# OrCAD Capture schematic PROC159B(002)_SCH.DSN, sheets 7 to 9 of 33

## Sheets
7 20. SOC-ICSS ETHERNET CONN: size C; title: SOC-ICSS ETHERNET CONN
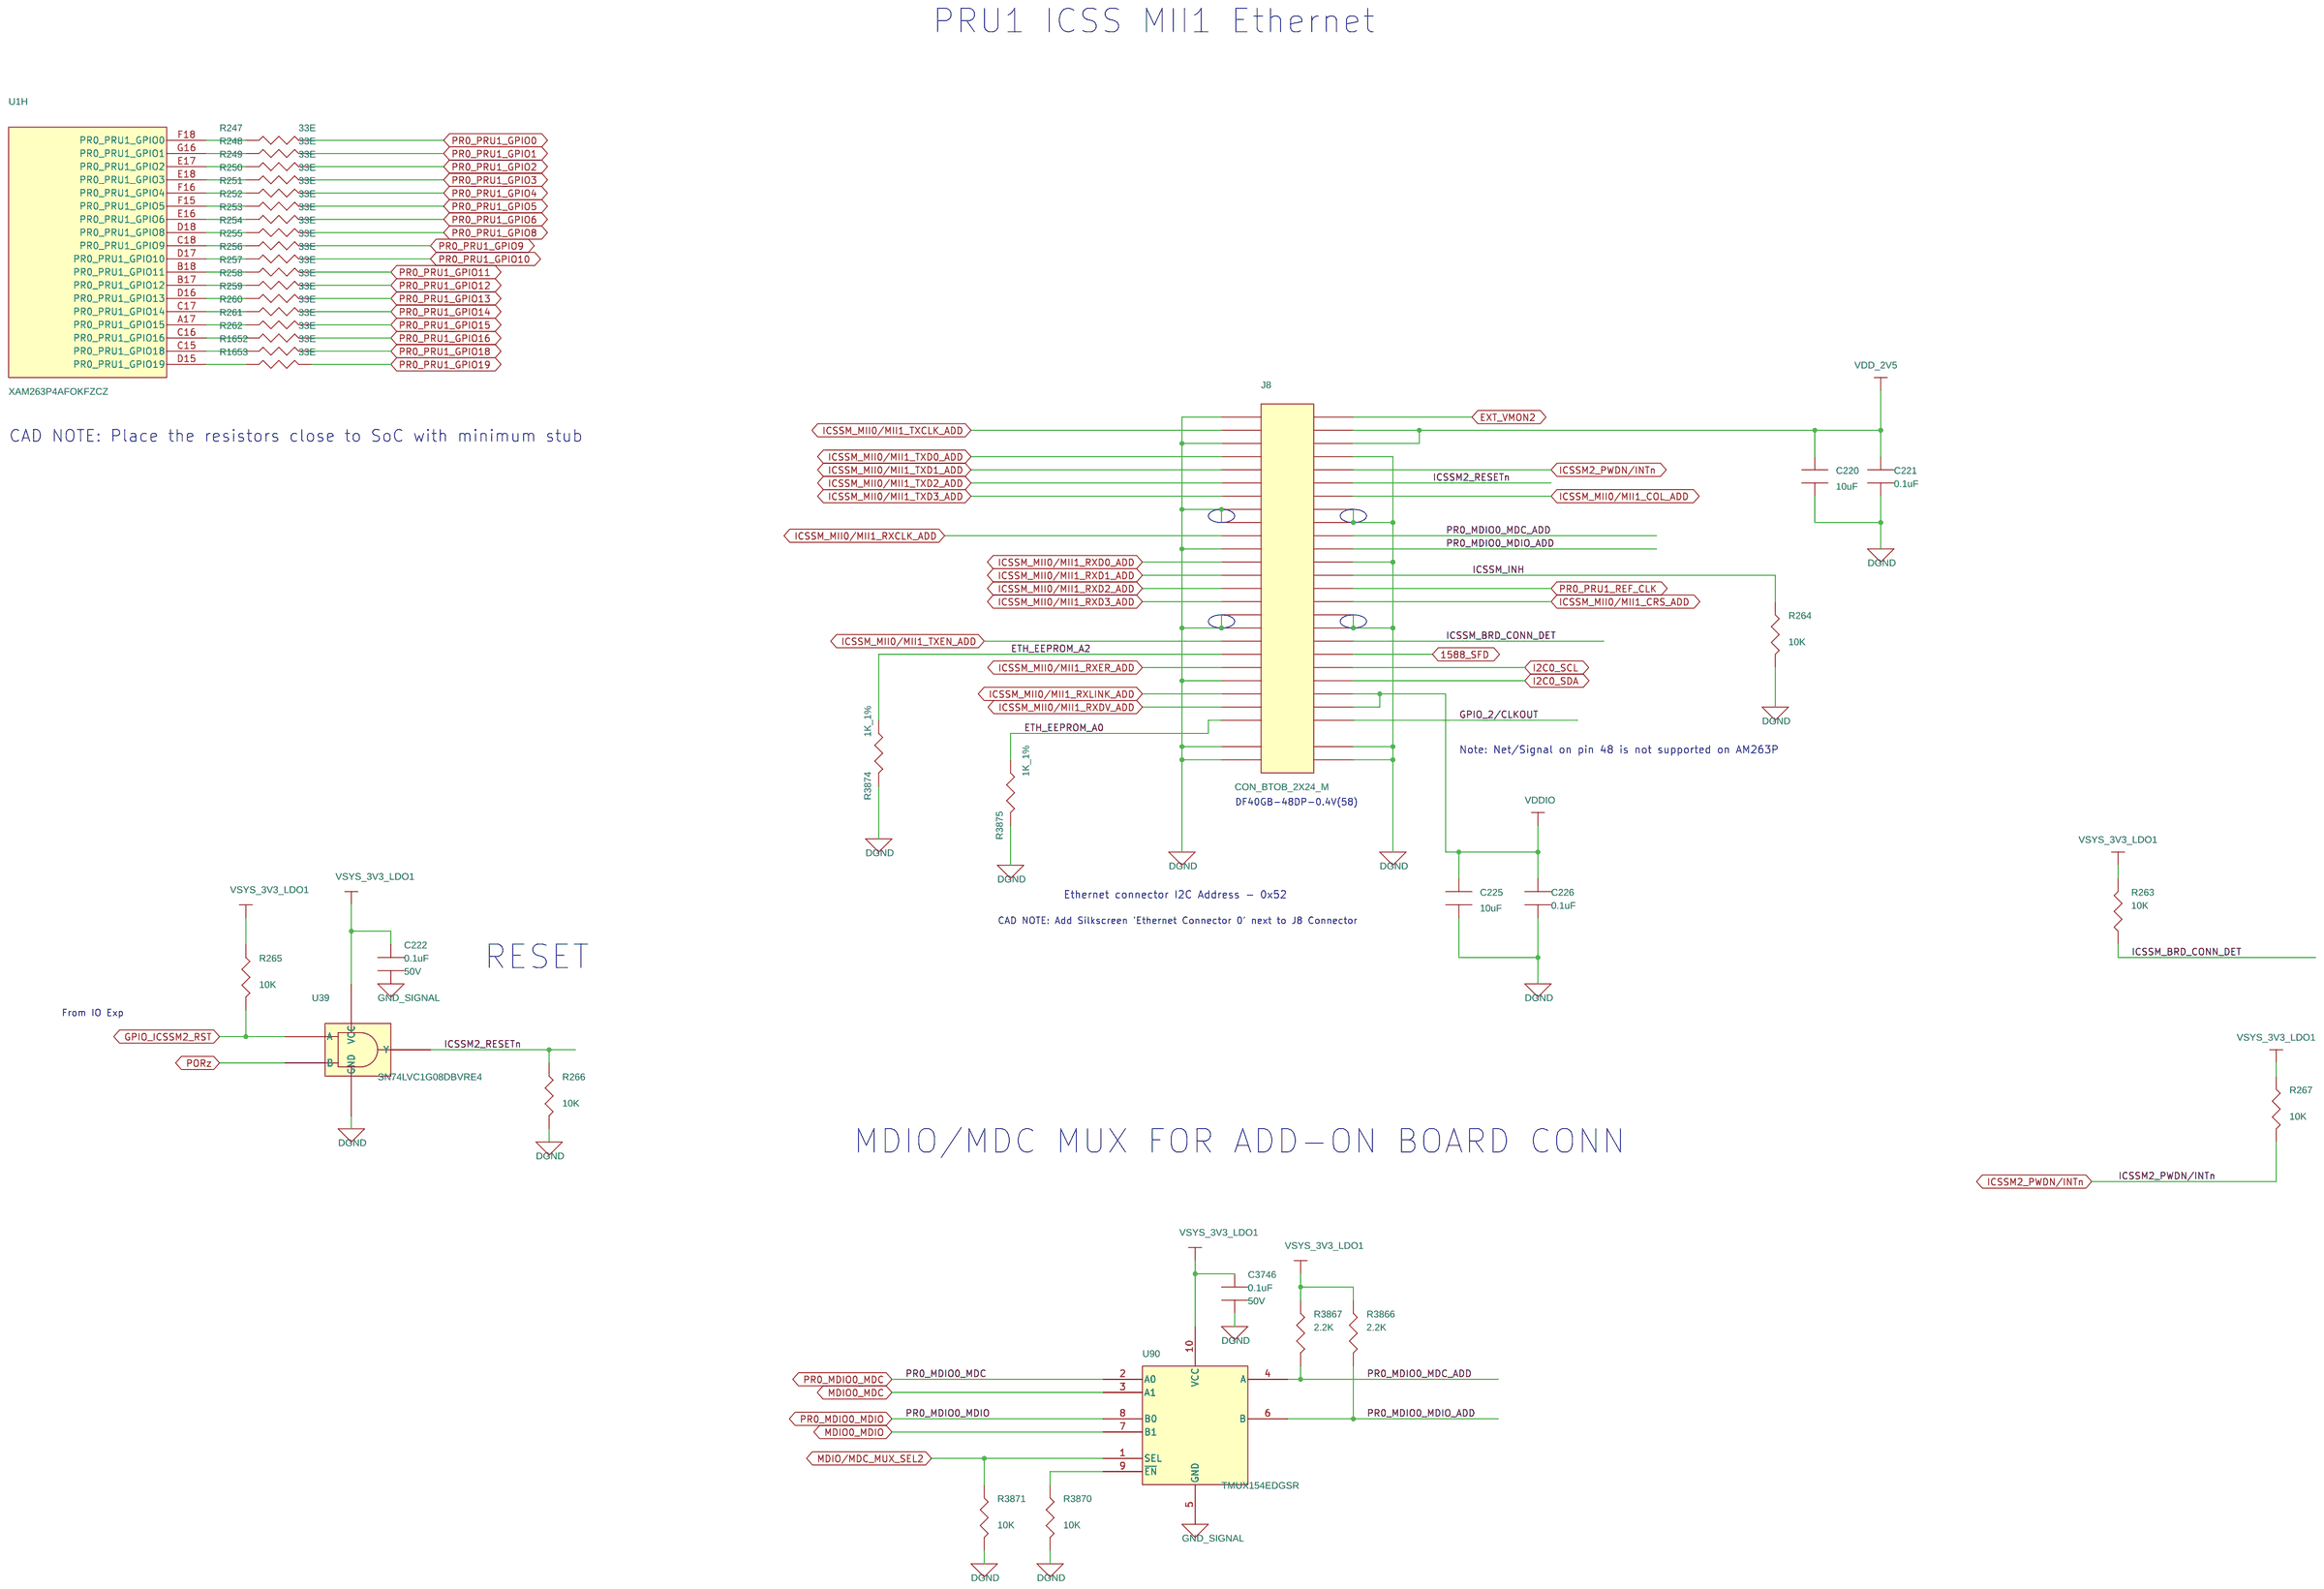
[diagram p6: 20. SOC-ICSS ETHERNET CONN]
8 13. SOC_POWER and GND: size C; title: SOC POWER AND GND
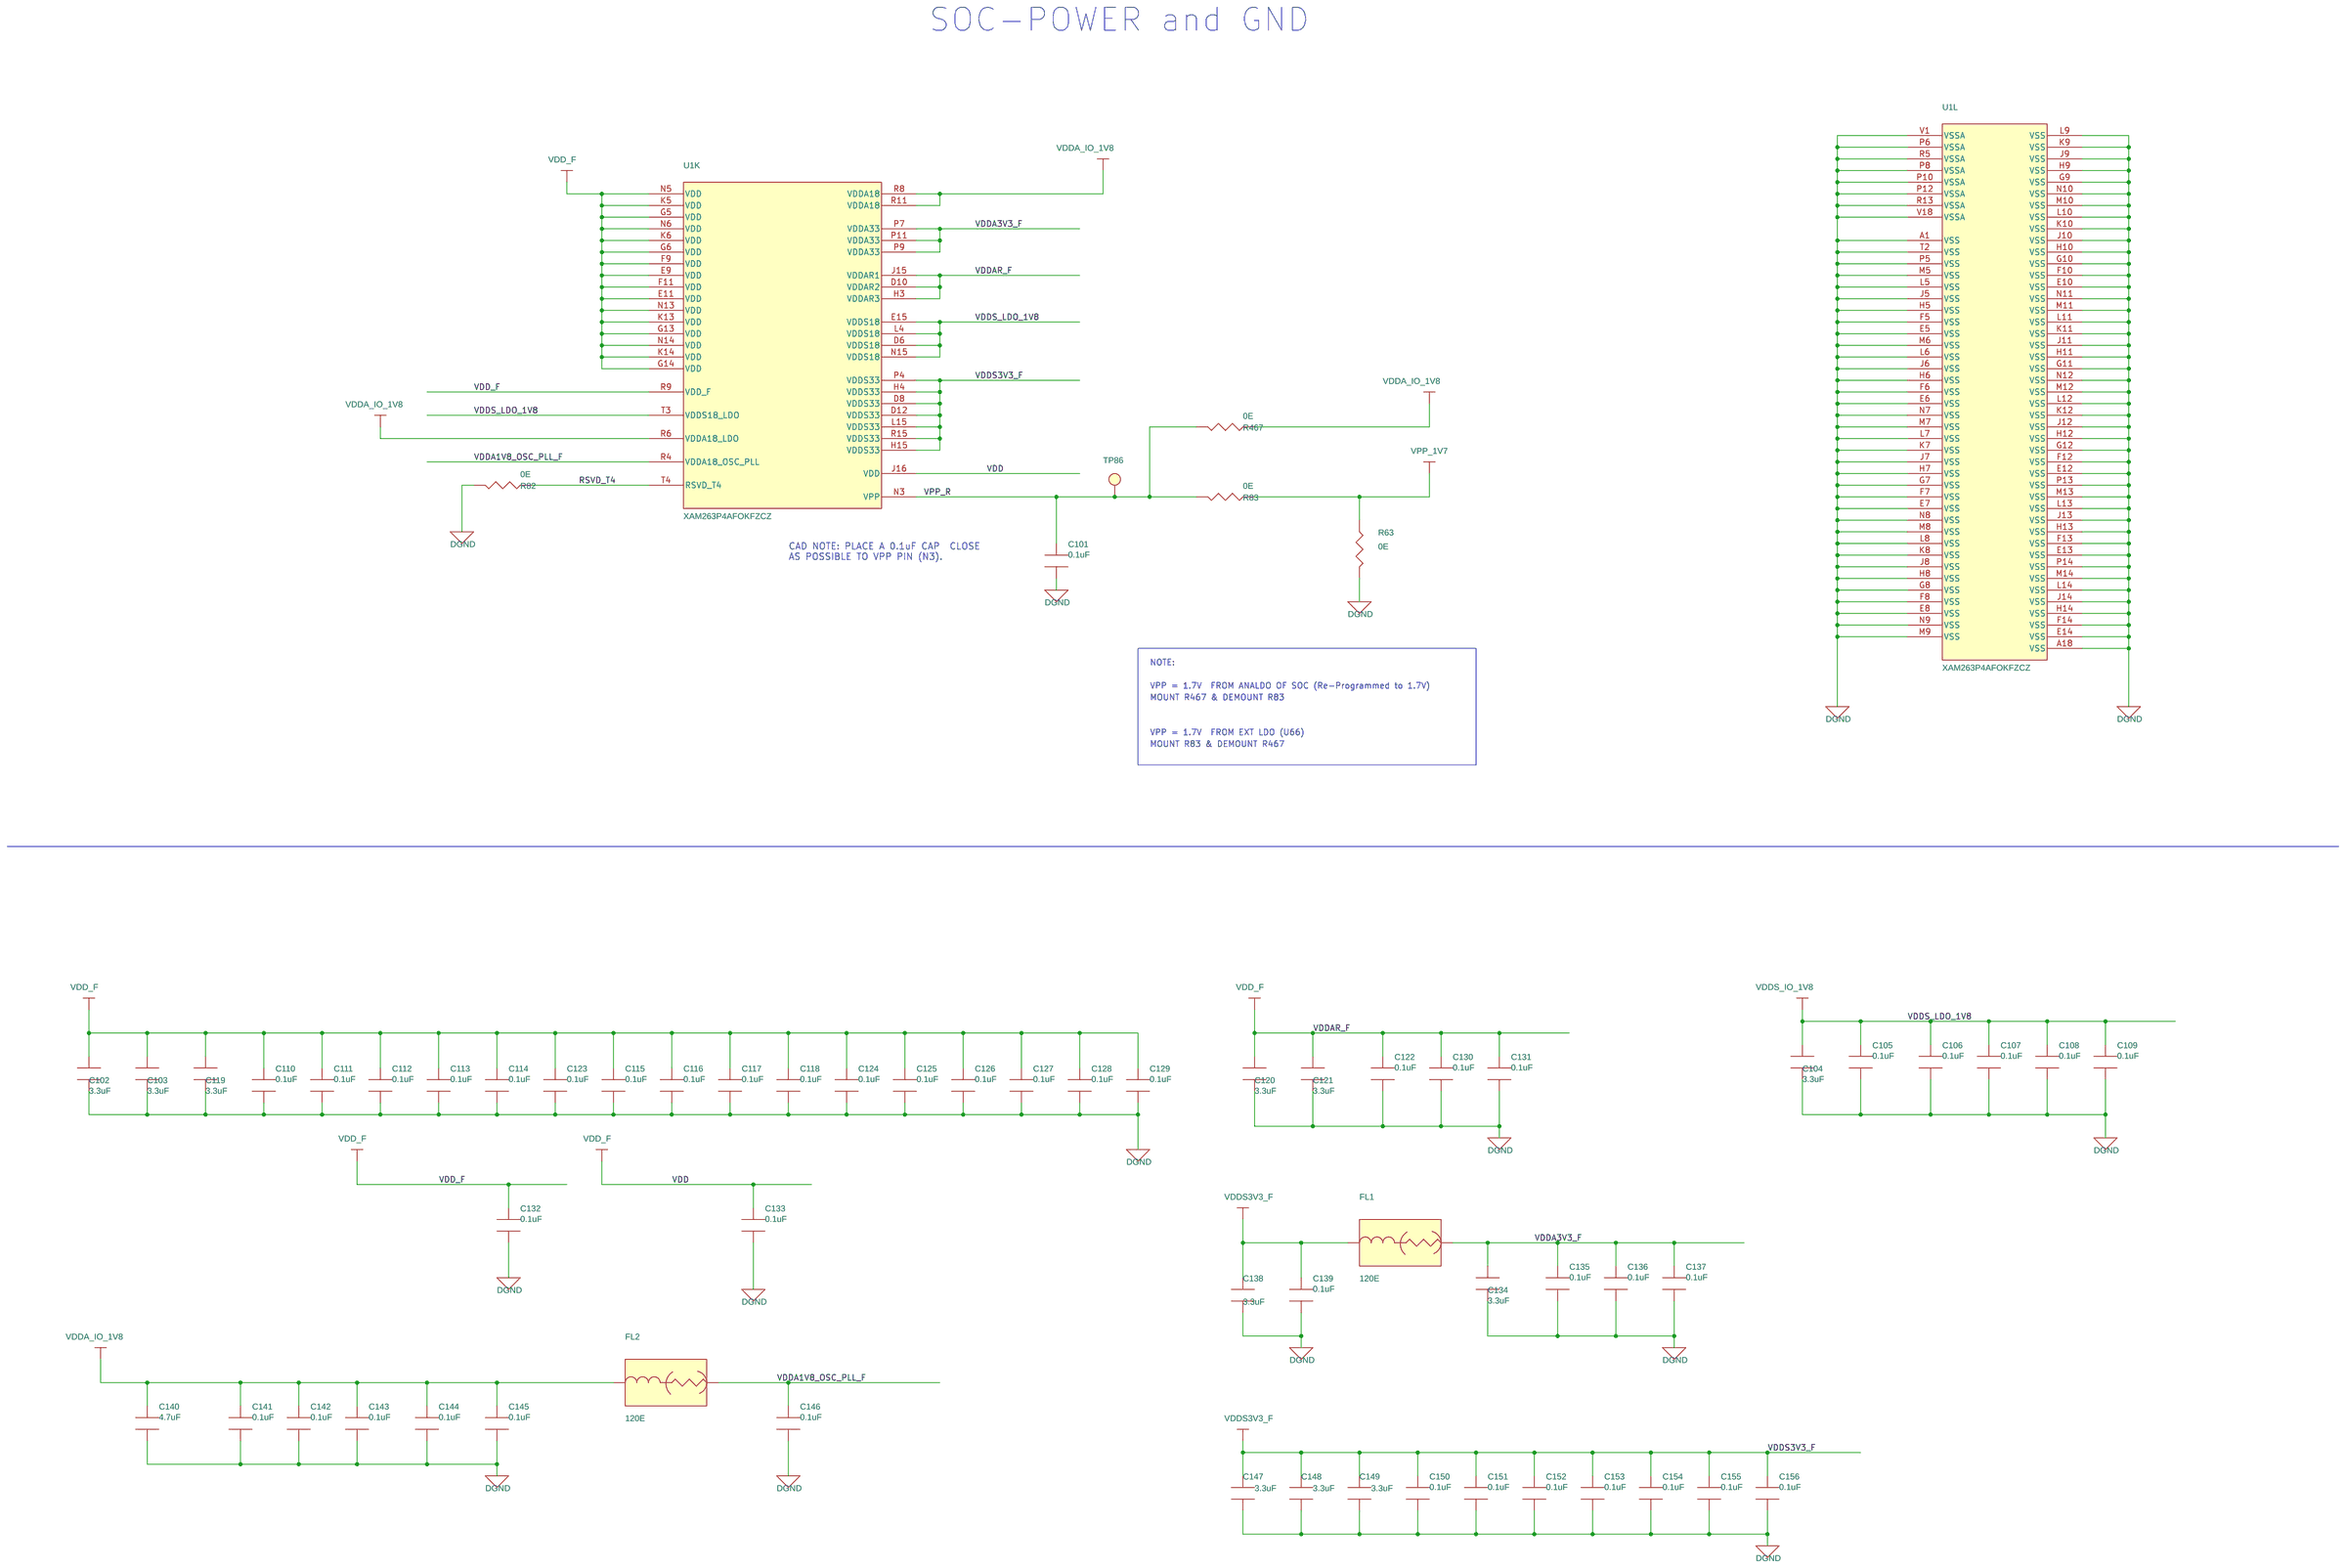
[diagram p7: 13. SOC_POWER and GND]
9 23. CLOCKS AND LIN1: size C; title: CLOCKS AND LIN1
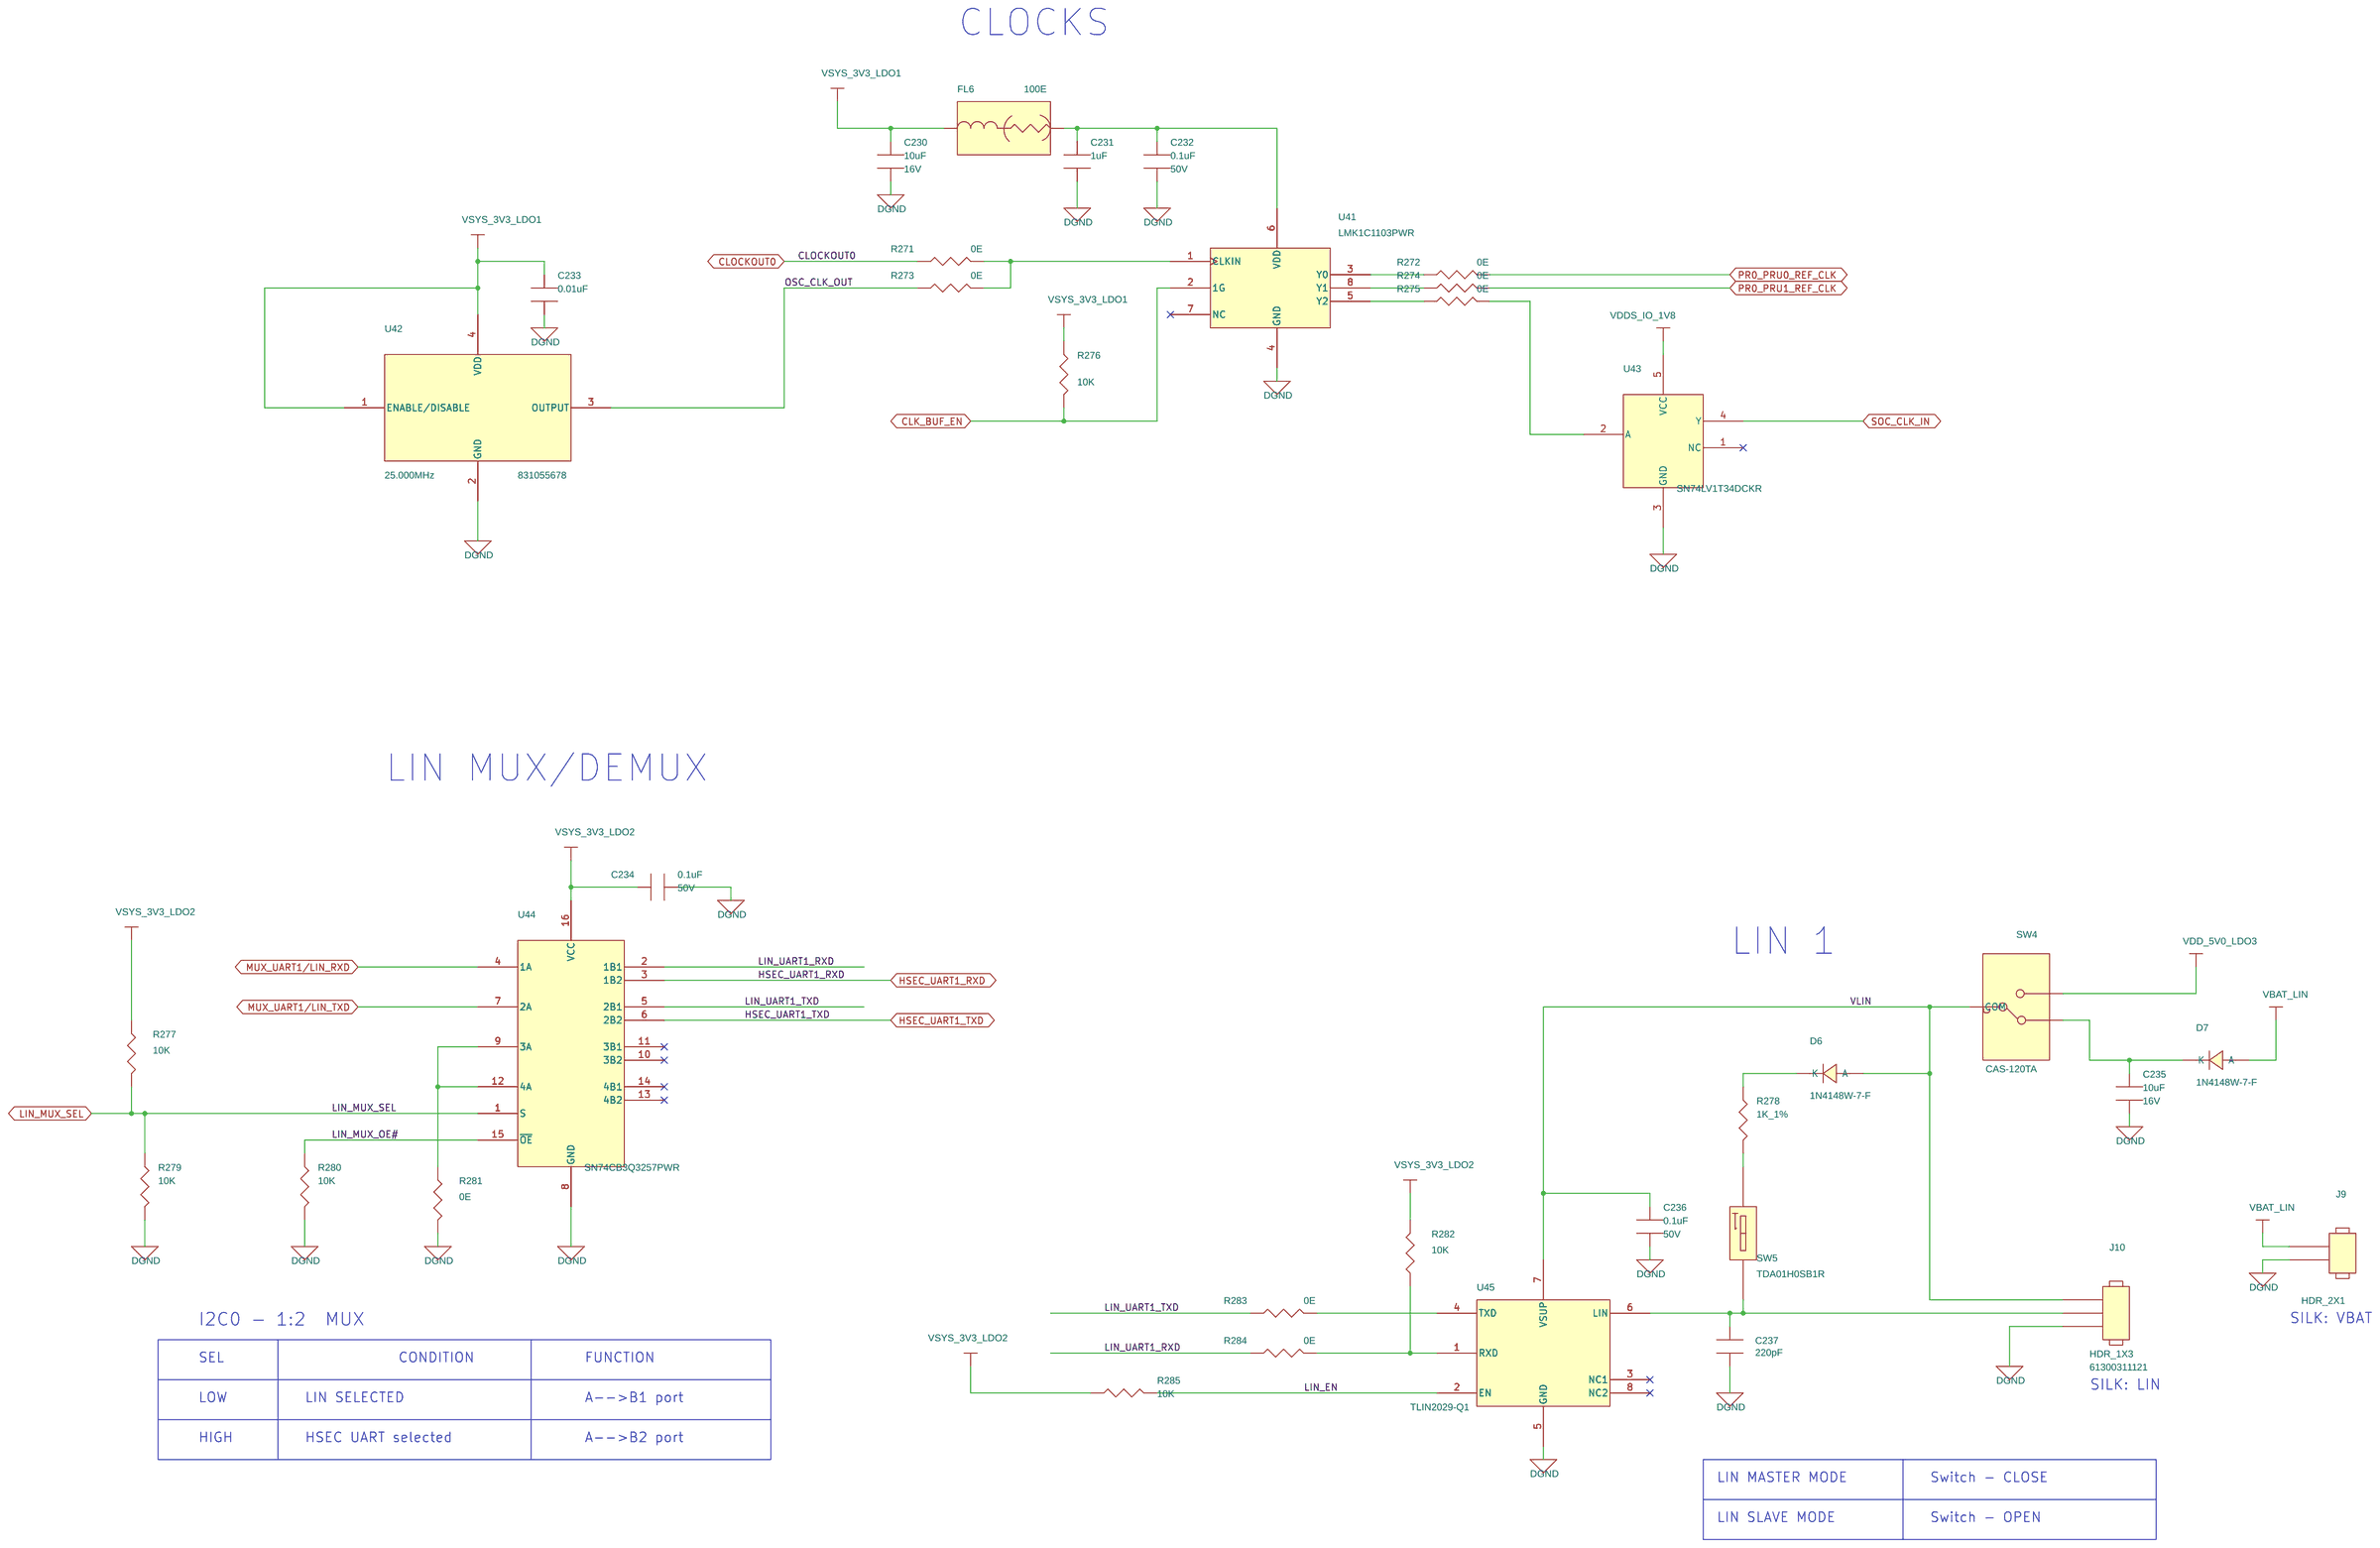
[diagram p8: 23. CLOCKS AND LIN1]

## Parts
sheet 13. SOC_POWER and GND
C101  0.1uF  [CAP0201_0-5]
C102  3.3uF  [CAP0603_1]
C103  3.3uF  [CAP0603_1]
C104  3.3uF  [CAP0603_1]
C105  0.1uF  [CAP0201_0-5]
C106  0.1uF  [CAP0201_0-5]
C107  0.1uF  [CAP0201_0-5]
C108  0.1uF  [CAP0402_0-75]
C109  0.1uF  [CAP0201_0-5]
C110  0.1uF  [CAP0201_0-5]
C111  0.1uF  [CAP0201_0-5]
C112  0.1uF  [CAP0201_0-5]
C113  0.1uF  [CAP0201_0-5]
C114  0.1uF  [CAP0201_0-5]
C115  0.1uF  [CAP0201_0-5]
C116  0.1uF  [CAP0201_0-5]
C117  0.1uF  [CAP0201_0-5]
C118  0.1uF  [CAP0201_0-5]
C119  3.3uF  [CAP0603_1]
C120  3.3uF  [CAP0603_1]
C121  3.3uF  [CAP0603_1]
C122  0.1uF  [CAP0201_0-5]
C123  0.1uF  [CAP0201_0-5]
C124  0.1uF  [CAP0201_0-5]
C125  0.1uF  [CAP0201_0-5]
C126  0.1uF  [CAP0201_0-5]
C127  0.1uF  [CAP0201_0-5]
C128  0.1uF  [CAP0201_0-5]
C129  0.1uF  [CAP0201_0-5]
C130  0.1uF  [CAP0201_0-5]
C131  0.1uF  [CAP0201_0-5]
C132  0.1uF  [CAP0201_0-5]
C133  0.1uF  [CAP0201_0-5]
C134  3.3uF  [CAP0603_1]
C135  0.1uF  [CAP0201_0-5]
C136  0.1uF  [CAP0201_0-5]
C137  0.1uF  [CAP0201_0-5]
C138  3.3uF  [CAP0603_1]
C139  0.1uF  [CAP0201_0-5]
C140  4.7uF  [CAP0603_1]
C141  0.1uF  [CAP0201_0-5]
C142  0.1uF  [CAP0201_0-5]
C143  0.1uF  [CAP0201_0-5]
C144  0.1uF  [CAP0201_0-5]
C145  0.1uF  [CAP0201_0-5]
C146  0.1uF  [CAP0201_0-5]
C147  3.3uF  [CAP0603_1]
C148  3.3uF  [CAP0603_1]
C149  3.3uF  [CAP0603_1]
C150  0.1uF  [CAP0201_0-5]
C151  0.1uF  [CAP0201_0-5]
C152  0.1uF  [CAP0201_0-5]
C153  0.1uF  [CAP0201_0-5]
C154  0.1uF  [CAP0201_0-5]
C155  0.1uF  [CAP0201_0-5]
C156  0.1uF  [CAP0201_0-5]
FL1  120E  [EMIFIL_BLM18R_0603_1]
FL2  120E  [EMIFIL_BLM18R_0603_1]
R63  0E  [RES0402_0-5]
R82  0E  [RES0402_0-5]
R83  0E  [RES0402_0-5]
R467  0E  [RES0402_0-5]
TP86  TP20_SMD  [TP20_SMD]
sheet 19. SOC-ICSS DP8386(Indust)
U1  XAM263P4AFOKFZCZ  [BGA324_31-49_590X590_1-4]  (sections A,B,C,D,E,F,G,H,I,J,K,L,M)
sheet 20. SOC-ICSS ETHERNET CONN
C220  10uF  [CAP0402_0-75]
C221  0.1uF  [CAP0402_0-75]
C222  0.1uF  [CAP0402_0-75]
C225  10uF  [CAP0402_0-75]
C226  0.1uF  [CAP0402_0-75]
C3746  0.1uF  [CAP0402_0-75]
J8  CON_BTOB_2X24_M  [CON_BTOB2X24_DF40GB-48DP_P_S_S_1-3]
R247  33E  [RES0402_0-5]
R248  33E  [RES0402_0-5]
R249  33E  [RES0402_0-5]
R250  33E  [RES0402_0-5]
R251  33E  [RES0402_0-5]
R252  33E  [RES0402_0-5]
R253  33E  [RES0402_0-5]
R254  33E  [RES0402_0-5]
R255  33E  [RES0402_0-5]
R256  33E  [RES0402_0-5]
R257  33E  [RES0402_0-5]
R258  33E  [RES0402_0-5]
R259  33E  [RES0402_0-5]
R260  33E  [RES0402_0-5]
R261  33E  [RES0402_0-5]
R262  33E  [RES0402_0-5]
R263  10K  [RES0201_0-5]
R264  10K  [RES0402_0-5]
R265  10K  [RES0402_0-5]
R266  10K  [RES0402_0-5]
R267  10K  [RES0402_0-5]
R1652  33E  [RES0402_0-5]
R1653  33E  [RES0402_0-5]
R3866  2.2K  [RES0402_0-5]
R3867  2.2K  [RES0402_0-5]
R3870  10K  [RES0402_0-5]
R3871  10K  [RES0402_0-5]
R3874  1K_1%  [RES0402_0-5]
R3875  1K_1%  [RES0402_0-5]
U39  SN74LVC1G08DBVRE4  [SOT23-5]
U90  TMUX154EDGSR  [MSOP10_19-68_120X120_1-1]
sheet 23. CLOCKS AND LIN1
C230  10uF  [CAP0603_1]
C231  1uF  [CAP0402_0-75]
C232  0.1uF  [CAP0402_0-75]
C233  0.01uF  [CAP0402_0-75]
C234  0.1uF  [CAP0402_0-75]
C235  10uF  [CAP0603_1]
C236  0.1uF  [CAP0402_0-75]
C237  220pF  [CAP0402_0-75]
D6  1N4148W-7-F  [DIO_SOD123_1-4]
D7  1N4148W-7-F  [DIO_SOD123_1-4]
FL6  100E  [EMIFIL_BLM18R_0603]
J9  HDR_2X1  [HDR_2X1_100_S_T]
J10  HDR_1X3  [HDR_1X3_100_S_T]
R271  0E  [RES0402_0-5]
R272  0E  [RES0402_0-5]
R273  0E  [RES0402_0-5]
R274  0E  [RES0402_0-5]
R275  0E  [RES0402_0-5]
R276  10K  [RES0402_0-5]
R277  10K  [RES0402_0-5]
R278  1K_1%  [RES0402_0-5]
R279  10K  [RES0402_0-5]
R280  10K  [RES0402_0-5]
R281  0E  [RES0402_0-5]
R282  10K  [RES0402_0-5]
R283  0E  [RES0402_0-5]
R284  0E  [RES0402_0-5]
R285  10K  [RES0402_0-5]
SW4  CAS-120TA  [SW3_CAS-120TA_215X100_SMD]
SW5  TDA01H0SB1R  [SW_TDA01H0S_240X90_SMD_2-3]
U41  LMK1C1103PWR  [TSSOP8_25-59_125X180_1-2]
U42  25.000MHz  [OSC4_ASEK_130X100_SMD_1-2]
U43  SN74LV1T34DCKR  [SC70-5_1-1]
U44  SN74CB3Q3257PWR  [TSSOP16_25-59_205X180]
U45  TLIN2029-Q1  [SOIC8_1-8]

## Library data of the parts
C101 C105-C107 C109-C118 C122-C133 C135-C137 C139 C141-C146 C150-C156 = CAP: CAP CERAMIC 0.1uF 10V 10% X5R 0201; Chkd/date: VASANTHA/061216; Crtd /date: MUDDU/190810; Custom_Duty: 15%; Customs_HS_Code: 85322990; Distributor_name: DIGIKEY; Distributor_part_number: 490-5881-1-ND; Footprint Path: Y:\MIS_DATABASE\Library\ALTIUM_TOOL\PCB_FOOTPRINTS\Altium_Footprint_Lib.PcbLib; Height: 0.33MM; Library Path: Y:\MIS_DATABASE\Library\ALTIUM_TOOL\SCHEMATICS_PARTS\MS_DISCRETE_Library.schlib; Mfr_name: MURATA; Mfr_part_number: GRM033R61A104KE15D; Mistral Part No: 120009050017-R; Package: 0201; Part_type: CAPACITORS\CERAMIC; Project: PB_BUGBASE; RoHS: RoHS; Temperature: -55°C+85°C; Tolerance: 10%; Voltage: 10V; Wattage: NA; Weight: 0.33mg; Datasheet: Y:\MIS_DATABASE\DATASHEETS\CAPACITORS\MURATA-GXX-SER_NOV17.PDF
C102-C104 C119-C121 C134 C138 C147-C149 = CAP: CAP CERAMIC 3.3uF 10V 10% X5R 0603; Chkd/date: MANIRAJA/210519; Crtd /date: MANIRAJA/210519; Custom_Duty: 15%; Customs_HS_Code: 85322990; Distributor_name: DIGIKEY; Distributor_part_number: 1276-1892-1-ND; Footprint Path: Y:\MIS_DATABASE\Library\ALTIUM_TOOL\PCB_FOOTPRINTS\Altium_Footprint_Lib.PcbLib; Height: 0.90MM; Library Path: Y:\MIS_DATABASE\Library\ALTIUM_TOOL\SCHEMATICS_PARTS\MS_DISCRETE_Library.schlib; Mfr_name: SAMSUNG; Mfr_part_number: CL10A335KP8NNNC; Mistral Part No: 120014070039-R; Package: 0603; Part_type: CAPACITORS\CERAMIC; Project: RFSU_RFTJ_CARD; RoHS: RoHS; Temperature: -55°C+85°C; Tolerance: 10%; Voltage: 10V; Wattage: NA; Weight: NA; Datasheet: Y:\MIS_DATABASE\DATASHEETS\CAPACITORS\CL10A335KP8NNNC.PDF
C108 = CAP: CAP CERAMIC 0.1uF 25V 10% X7R 0402; Chkd/date: MANIRAJA/190218; Crtd /date: ALVY/160218; Custom_Duty: 15%; Customs_HS_Code: 85322990; Distributor_name: DIGIKEY; Distributor_part_number: 490-10698-1-ND; Footprint Path: Y:\MIS_DATABASE\Library\ALTIUM_TOOL\PCB_FOOTPRINTS\Altium_Footprint_Lib.PcbLib; Height: 0.55MM; Library Path: Y:\MIS_DATABASE\Library\ALTIUM_TOOL\SCHEMATICS_PARTS\MS_DISCRETE_Library.schlib; Mfr_name: MURATA; Mfr_part_number: GRM155R71E104KE14D; Mistral Part No: 120013060012-R; Package: 0402; Part_type: CAPACITORS\CERAMIC; Project: GRACO SMART MODULE; RoHS: RoHS; Temperature: -55°C+125°C; Tolerance: 10%; Voltage: 25V; Wattage: NA; Weight: 6mg; Datasheet: Y:\MIS_DATABASE\DATASHEETS\CAPACITORS\GRM155R71E104KE14.PDF
C140 = CAP: CAP CERAMIC 4.7uF 25V 10% X6S 0603; Chkd/date: MANIRAJA/241018; Crtd /date: ALVY/241018; Custom_Duty: 15%; Customs_HS_Code: 85322990; Distributor_name: DIGIKEY; Distributor_part_number: 490-7199-1-ND; Footprint Path: Y:\MIS_DATABASE\Library\ALTIUM_TOOL\PCB_FOOTPRINTS\Altium_Footprint_Lib.PcbLib; Height: 1.00MM; Library Path: Y:\MIS_DATABASE\Library\ALTIUM_TOOL\SCHEMATICS_PARTS\MS_DISCRETE_Library.schlib; Mfr_name: MURATA; Mfr_part_number: GRM188C81E475KE11D; Mistral Part No: 120018100056-R; Package: 0603; Part_type: CAPACITORS\CERAMIC; Project: TI_J7ES_EVM_CP; RoHS: RoHS; Temperature: -55°C+105°C; Tolerance: 10%; Voltage: 25V; Wattage: NA; Weight: 6.3mg; Datasheet: Y:\MIS_DATABASE\DATASHEETS\CAPACITORS\GRM188C81E475KE11D.PDF
FL1 FL2 = EMIFILTER_IND: FERRITE BEAD 120E 2A 0603; Chkd/date: VASANTHA/061216; Crtd /date: MUDDU/190610; Custom_Duty: 24%; Customs_HS_Code: 85437099; Distributor_name: DIGIKEY; Distributor_part_number: 490-3991-1-ND; Footprint Path: Y:\MIS_DATABASE\Library\ALTIUM_TOOL\PCB_FOOTPRINTS\Altium_Footprint_Lib.PcbLib; Height: 0.95MM; Library Path: Y:\MIS_DATABASE\Library\ALTIUM_TOOL\SCHEMATICS_PARTS\MS_FILTER_Library.schlib; Mfr_name: MURATA; Mfr_part_number: BLM18EG121SN1D; Mistral Part No: 130010060030-R; Package: 0603; Part_type: FILTER; Project: CENTAURUS; RoHS: RoHS; Temperature: -55°C+125°C; Tolerance: NA; Voltage: NA; Wattage: NA; Weight: NA; Datasheet: Y:\MIS_DATABASE\DATASHEETS\DISCRETES\INDUCTORS\BLM18E.PDF
R63 R82 R83 R281 R467 = RESISTOR: RES 0E 1/10W JUMPER 0402; Chkd/date: VASANTHA/061216; Crtd /date: NAVEED/201014; Custom_Duty: 15%; Customs_HS_Code: 85332119; Distributor_name: DIGIKEY; Distributor_part_number: P0.0JCT-ND; Footprint Path: Y:\MIS_DATABASE\Library\ALTIUM_TOOL\PCB_FOOTPRINTS\Altium_Footprint_Lib.PcbLib; Height: 0.40MM; IBISSP_MODLES: VALUE REPEATING 2 TIME; Library Path: Y:\MIS_DATABASE\Library\ALTIUM_TOOL\SCHEMATICS_PARTS\MS_DISCRETE_Library.schlib; Mfr_name: PANASONIC-ECG; Mfr_part_number: ERJ-2GE0R00X; Mistral Part No: 110018030052-R; Package: 0402; Part_type: RESISTORS\FIXED; Project: AEGIS POM; RoHS: RoHS; Temperature: -55°C+155°C; Tolerance: NA; Voltage: NA; Wattage: 1/10W; Weight: 0.8mg; Datasheet: Y:\MIS_DATABASE\DATASHEETS\RESISTORS\PAN-ERJSER_NOV17.PDF
TP86 = TESTPOINT: TESTPOINT CIR 20 SMD; Chkd/date: SHREESHAIL/171006; Crtd /date: MAZHAR/171006; Custom_Duty: NA; Customs_HS_Code: NA; Distributor_name: NA; Distributor_part_number: NA; Footprint Path: Y:\MIS_DATABASE\Library\ALTIUM_TOOL\PCB_FOOTPRINTS\Altium_Footprint_Lib.PcbLib; Height: NA; Library Path: Y:\MIS_DATABASE\Library\ALTIUM_TOOL\SCHEMATICS_PARTS\MS_DISCRETE_Library.schlib; MECHANICAL 3D STEP FILE: NA; Mfr_name: LOCAL; Mistral Part No: NA; Package: SMD; Project: BT MODULE_CSRBC04; RoHS: NA; Temperature: NA; Tolerance: NA; Voltage: NA; Wattage: NA; Weight: NA; Datasheet: NA
U1 = XAM263P4ASOKFZCZ_BGA324: IC SIP AM263P SoC BGA324; Chkd/date: PRADEEP/030124; Crtd /date: PRADEEP/030124; Custom_Duty: 15%; Customs_HS_Code: 85423100; Distributor_name: NA; Distributor_part_number: NA; Footprint Path: Y:\MIS_DATABASE\Library\ALTIUM_TOOL\PCB_FOOTPRINTS\Altium_Footprint_Lib.PcbLib; Height: 1.40MM; MECHANICAL 3D STEP FILE: NA; Mfr_name: TEXAS INSTRUMENTS; Mistral Part No: 141324010001; Package: BGA324; Part_type: ICS\DIGITAL\FPGA; Project: AM263P_CC; RoHS: RoHS; Temperature: NA; Tolerance: NA; Voltage: NA; Wattage: NA; Weight: NA; Datasheet: Y:\MIS_DATABASE\DATASHEETS\ICS\INTERFACE\ZCZ0324A.PDF
C220 C225 = CAP: CAP CERAMIC 10uF 10V 20% X5R 0402; Chkd/date: MANIRAJA/300520; Crtd /date: ALVY/260520; Custom_Duty: 15%; Customs_HS_Code: 85322990; Distributor_name: DIGIKEY; Distributor_part_number: 490-GRM155R61A106ME11DTR-ND; Footprint Path: Y:\MIS_DATABASE\Library\ALTIUM_TOOL\PCB_FOOTPRINTS\Altium_Footprint_Lib.PcbLib; Height: 0.55MM; Library Path: Y:\MIS_DATABASE\Library\ALTIUM_TOOL\SCHEMATICS_PARTS\MS_DISCRETE_Library.schlib; Mfr_name: MURATA; Mfr_part_number: GRM155R61A106ME11D; Mistral Part No: 120013110019-R; Package: 0402; Part_type: CAPACITORS\CERAMIC; Project: QCS610_NANOSOM; RoHS: RoHS; Temperature: -55°C+85°C; Tolerance: 20%; Voltage: 10V; Wattage: NA; Weight: 3.1mg; Datasheet: Y:\MIS_DATABASE\DATASHEETS\CAPACITORS\MURATA-GXX-SER_NOV17.PDF
C221 C226 C232 C236 = CAP: CAP CERAMIC 0.1uF 50V 10% X7R 0402; Chkd/date: MANIRAJA/261020; Crtd /date: ALVY/211020; Custom_Duty: 15%; Customs_HS_Code: 85322990; Distributor_name: DIGIKEY; Distributor_part_number: 490-10700-1-ND; Footprint Path: Y:\MIS_DATABASE\Library\ALTIUM_TOOL\PCB_FOOTPRINTS\Altium_Footprint_Lib.PcbLib; Height: 0.55MM; Library Path: Y:\MIS_DATABASE\Library\ALTIUM_TOOL\SCHEMATICS_PARTS\MS_DISCRETE_Library.schlib; Mfr_name: MURATA; Mfr_part_number: GRM155R71H104KE14D; Mistral Part No: 120011100014-R; Package: 0402; Part_type: CAPACITORS\CERAMIC; Project: J7_CP; RoHS: RoHS; Temperature: -55°C+125°C; Tolerance: 10%; Voltage: 50V; Wattage: NA; Weight: 3.1mg; Datasheet: Y:\MIS_DATABASE\DATASHEETS\CAPACITORS\GRM155R71H104KE14.PDF
C222 C234 C3746 = CAP: CAP CERAMIC 0.1uF 50V 10% X7R 0402; Automotive Alternate_mfr_name: TDK; Automotive Alternate_mfr_part_number: CGA2B3X7R1H104K050BB; Chkd/date: MANIRAJA/261020; Crtd /date: ALVY/211020; Custom_Duty: 15%; Customs_HS_Code: 85322990; Direct Alternate_mfr_name: TDK; Direct Alternate_mfr_part_number: C1005X7R1H104K050BE; Distributor_name: DIGIKEY; Distributor_part_number: 490-10700-1-ND; Footprint Path: Y:\MIS_DATABASE\Library\ALTIUM_TOOL\PCB_FOOTPRINTS\Altium_Footprint_Lib.PcbLib; Height: 0.55MM; Library Path: Y:\MIS_DATABASE\Library\ALTIUM_TOOL\SCHEMATICS_PARTS\MS_DISCRETE_Library.schlib; Mfr_name: MURATA; Mfr_part_number: GRM155R71H104KE14D; Mistral Part No: 120011100014-R; Package: 0402; Part_type: CAPACITORS\CERAMIC; Project: J7_CP; RoHS: RoHS; Temperature: -55°C+125°C; Tolerance: 10%; Voltage: 50V; Wattage: NA; Weight: 3.1mg; Datasheet: Y:\MIS_DATABASE\DATASHEETS\CAPACITORS\GRM155R71H104KE14.PDF
J8 = CON_BTOB_24X2_M_SH4: CON BTOB 2X24 0.40MM PITCH MALE ST SMD; Chkd/date: PRAVEEN/290323; Crtd /date: PRAVEEN/290323; Custom_Duty: 24%; Customs_HS_Code: 85369090; Distributor_name: DIGIKEY; Distributor_part_number: H124956CT-ND; Footprint Path: Y:\MIS_DATABASE\Library\ALTIUM_TOOL\PCB_FOOTPRINTS\Altium_Footprint_Lib.PcbLib; Height: 1.30MM; Library Path: Y:\MIS_DATABASE\Library\ALTIUM_TOOL\SCHEMATICS_PARTS\MS_CONNECTOR_Library.schlib; Mfr_name: HIROSE ELECTRIC EUROPE; Mfr_part_number: DF40GB-48DP-0.4V(58); Mistral Part No: 150023030029-R; Package: SMD; Part_type: CONNECTOR\BTOB; Project: AM263P_CC; RoHS: RoHS; Temperature: -35°C+85°C; Tolerance: NA; Voltage: NA; Wattage: NA; Weight: NA; Datasheet: Y:\MIS_DATABASE\DATASHEETS\CONNECTORS\DF40GB-48DP-0.4V.PDF
R247-R262 R1652 R1653 = RESISTOR: RES 33E 1/10W 5% 0402; Chkd/date: VASANTHA/201216; Crtd /date: GEETHA/190406; Custom_Duty: 15%; Customs_HS_Code: 85332119; Distributor_name: DIGIKEY; Distributor_part_number: P33JCT-ND; Footprint Path: Y:\MIS_DATABASE\Library\ALTIUM_TOOL\PCB_FOOTPRINTS\Altium_Footprint_Lib.PcbLib; Height: 0.40MM; Library Path: Y:\MIS_DATABASE\Library\ALTIUM_TOOL\SCHEMATICS_PARTS\MS_DISCRETE_Library.schlib; Mfr_name: PANASONIC-ECG; Mfr_part_number: ERJ-2GEJ330X; Mistral Part No: 110009030699-R; Package: 0402; Part_type: RESISTORS\FIXED; Project: RED EYE; RoHS: RoHS; Temperature: -55°C+155°C; Tolerance: 5%; Voltage: NA; Wattage: 1/10W; Weight: 0.8mg; Datasheet: Y:\MIS_DATABASE\DATASHEETS\RESISTORS\PAN-ERJSER_NOV17.PDF
R263 = RESISTOR: RES 10K 1/20W 5% 0201; Chkd/date: MANIRAJA/050517; Crtd /date: MANIRAJA/050517; Custom_Duty: 15%; Customs_HS_Code: 85332119; Distributor_name: DIGIKEY; Distributor_part_number: 311-10KNCT-ND; Footprint Path: Y:\MIS_DATABASE\Library\ALTIUM_TOOL\PCB_FOOTPRINTS\Altium_Footprint_Lib.PcbLib; Height: 0.26MM; Library Path: Y:\MIS_DATABASE\Library\ALTIUM_TOOL\SCHEMATICS_PARTS\MS_DISCRETE_Library.schlib; Mfr_name: YAGEO AMERICA; Mfr_part_number: RC0201JR-0710KL; Mistral Part No: 110010070051-R; Package: 0201; Part_type: RESISTORS\FIXED; Project: GOLDEN-I LITE; RoHS: RoHS; Temperature: -55°C+125°C; Tolerance: 5%; Voltage: NA; Wattage: 1/20W; Weight: 0.17mg; Datasheet: Y:\MIS_DATABASE\DATASHEETS\RESISTORS\RCXXXXL-SER_MAR18.PDF
R264-R267 R276 R277 R282 R285 R3870 R3871 = RESISTOR: RES 10K 1/16W 5% 0402; Chkd/date: VASANTHA/061216; Crtd /date: MAZHAR/230805; Custom_Duty: 15%; Customs_HS_Code: 85332119; Distributor_name: DIGIKEY; Distributor_part_number: 311-10KJRCT-ND; Footprint Path: Y:\MIS_DATABASE\Library\ALTIUM_TOOL\PCB_FOOTPRINTS\Altium_Footprint_Lib.PcbLib; Height: 0.40MM; Library Path: Y:\MIS_DATABASE\Library\ALTIUM_TOOL\SCHEMATICS_PARTS\MS_DISCRETE_Library.schlib; Mfr_name: YAGEO AMERICA; Mfr_part_number: RC0402JR-0710KL; Mistral Part No: 110011060021-R; Package: 0402; Part_type: RESISTORS\FIXED; Project: HSE; RoHS: RoHS; Temperature: -55°C+155°C; Tolerance: 5%; Voltage: NA; Wattage: 1/16W; Weight: 0.65mg; Datasheet: Y:\MIS_DATABASE\DATASHEETS\RESISTORS\RCXXXXL-SER_MAR18.PDF
R3866 R3867 = RESISTOR: RES 2.2K 1/10W 5% 0402; Chkd/date: SHREESHAIL/210406; Crtd /date: GEETHA/200406; Custom_Duty: 15%; Customs_HS_Code: 85332119; Distributor_name: DIGIKEY; Distributor_part_number: P2.2KJCT-ND; Footprint Path: Y:\MIS_DATABASE\Library\ALTIUM_TOOL\PCB_FOOTPRINTS\Altium_Footprint_Lib.PcbLib; Height: 0.40MM; Library Path: Y:\MIS_DATABASE\Library\ALTIUM_TOOL\SCHEMATICS_PARTS\MS_DISCRETE_Library.schlib; Mfr_name: PANASONIC-ECG; Mfr_part_number: ERJ-2GEJ222X; Mistral Part No: 110009030429-R; Package: 0402; Part_type: RESISTORS\FIXED; Project: RED EYE; RoHS: RoHS; Temperature: -55°C+155°C; Tolerance: 5%; Voltage: NA; Wattage: 1/10W; Weight: 0.8mg; Datasheet: Y:\MIS_DATABASE\DATASHEETS\RESISTORS\PAN-ERJSER_NOV17.PDF
R278 R3874 R3875 = RESISTOR: RES 1K 1/10W 1% 0402; Chkd/date: VASANTHA/281216; Crtd /date: MAZHAR/150506; Custom_Duty: 15%; Customs_HS_Code: 85332119; Distributor_name: DIGIKEY; Distributor_part_number: P1.00KLCT-ND; Footprint Path: Y:\MIS_DATABASE\Library\ALTIUM_TOOL\PCB_FOOTPRINTS\Altium_Footprint_Lib.PcbLib; Height: 0.40MM; Library Path: Y:\MIS_DATABASE\Library\ALTIUM_TOOL\SCHEMATICS_PARTS\MS_DISCRETE_Library.schlib; Mfr_name: PANASONIC-ECG; Mfr_part_number: ERJ-2RKF1001X; Mistral Part No: 110009030411-R; Package: 0402; Part_type: RESISTORS\FIXED; Project: VOCERA; RoHS: RoHS; Temperature: -55°C+155°C; Tolerance: 1%; Voltage: NA; Wattage: 1/10W; Weight: 0.8mg; Datasheet: Y:\MIS_DATABASE\DATASHEETS\RESISTORS\PAN-ERJSER_NOV17.PDF
U39 = SN74LVC1G08DBVRE4_SOT23-5: IC SINGLE 2-INPUT POSITIVE AND GATE SOT23-5; Automotive Alternate_mfr_name: TEXAS INSTRUMENTS; Automotive Alternate_mfr_part_number: SN74LVC1G08QDBVRQ1; Chkd/date: SUHAS/221010; Crtd /date: USMAN/151008; Custom_Duty: 15%; Customs_HS_Code: 85423100; Distributor_name: DIGIKEY; Distributor_part_number: SN74LVC1G08DBVRE4-ND; Height: 1.45MM; Mfr_name: TEXAS INSTRUMENTS; Mistral Part No: 141009060026-R; Part_type: ICS\DIGITAL\GATES; Project: KHAN_MAIN; RoHS: Sb/ Br FREE; Temperature: -40°C+85°C; Datasheet: Y:\MIS_DATABASE\DATASHEETS\ICS\DIGITAL\GATES\SN74LVC1G08.PDF
U90 = TMUX154EDGSR_VSSOP10: IC ESD PROTECTED 2-CH 2:1 SWITCH WITH POWERED-OFF PROTECTION VSSOP10; Chkd/date: MANIRAJA/040918; Crtd /date: MANIRAJA/040918; Custom_Duty: 15%; Customs_HS_Code: 85423100; Distributor_name: DIGIKEY; Distributor_part_number: 296-48347-1-ND; Footprint Path: Y:\MIS_DATABASE\Library\ALTIUM_TOOL\PCB_FOOTPRINTS\Altium_Footprint_Lib.PcbLib; Height: 1.10MM; Library Path: Y:\MIS_DATABASE\Library\ALTIUM_TOOL\SCHEMATICS_PARTS\MS_ANALOG-APPLICATION_Library.schlib; Mfr_name: TEXAS INSTRUMENTS; Mistral Part No: 140118090001-R; Package: VSSOP10; Part_type: ICS\ANALOG\SWITCH; Project: DLRL_DFP_ATRUC CARD; RoHS: RoHS; Temperature: -40°C+85°C; Tolerance: NA; Voltage: NA; Wattage: NA; Weight: NA; Datasheet: Y:\MIS_DATABASE\DATASHEETS\ICS\ANALOG\TMUX154EXXX.PDF
C230 C235 = CAP: CAP CERAMIC 10uF 16V 20% X6S 0603; Chkd/date: VASANTHA/170117; Crtd /date: VASANTHA/170117; Custom_Duty: 15%; Customs_HS_Code: 85322990; Distributor_name: DIGIKEY; Distributor_part_number: 490-7198-1-ND; Footprint Path: Y:\MIS_DATABASE\Library\ALTIUM_TOOL\PCB_FOOTPRINTS\Altium_Footprint_Lib.PcbLib; Height: 0.90MM; Library Path: Y:\MIS_DATABASE\Library\ALTIUM_TOOL\SCHEMATICS_PARTS\MS_DISCRETE_Library.schlib; Mfr_name: MURATA; Mfr_part_number: GRM188C81C106MA73D; Mistral Part No: 120017010004-R; Package: 0603; Part_type: CAPACITORS\CERAMIC; Project: TRMM_SMART-M_PS; RoHS: RoHS; Temperature: -55°C+105°C; Tolerance: 20%; Voltage: 16V; Wattage: NA; Weight: 6.3mg; Datasheet: Y:\MIS_DATABASE\DATASHEETS\CAPACITORS\MURATA-GXX-SER_NOV17.PDF
C231 = CAP: CAP CERAMIC 1uF 25V 10% X6S 0402; Chkd/date: MANIRAJA/140518; Crtd /date: ALVY/140518; Custom_Duty: 15%; Customs_HS_Code: 85322990; Distributor_name: DIGIKEY; Distributor_part_number: 490-10014-1-ND; Footprint Path: Y:\MIS_DATABASE\Library\ALTIUM_TOOL\PCB_FOOTPRINTS\Altium_Footprint_Lib.PcbLib; Height: 0.60MM; Library Path: Y:\MIS_DATABASE\Library\ALTIUM_TOOL\SCHEMATICS_PARTS\MS_DISCRETE_Library.schlib; Mfr_name: MURATA; Mfr_part_number: GRM155C81E105KE11D; Mistral Part No: 120018050004-R; Package: 0402; Part_type: CAPACITORS\CERAMIC; Project: TI_SVB_MAXWELL_DUT; RoHS: RoHS; Temperature: -55°C+105°C; Tolerance: 10%; Voltage: 25V; Wattage: NA; Weight: 6mg; Datasheet: Y:\MIS_DATABASE\DATASHEETS\CAPACITORS\GRM155C81E105KE11X.PDF
C233 = CAP: CAP CERAMIC 0.01uF 50V 10% X7R 0402; Chkd/date: MANIRAJA/280319; Crtd /date: MANIRAJA/280319; Custom_Duty: 15%; Customs_HS_Code: 85322990; Distributor_name: DIGIKEY; Distributor_part_number: 490-4516-1-ND; Footprint Path: Y:\MIS_DATABASE\Library\ALTIUM_TOOL\PCB_FOOTPRINTS\Altium_Footprint_Lib.PcbLib; Height: 0.55MM; Library Path: Y:\MIS_DATABASE\Library\ALTIUM_TOOL\SCHEMATICS_PARTS\MS_DISCRETE_Library.schlib; Mfr_name: MURATA; Mfr_part_number: GRM155R71H103KA88D; Mistral Part No: 120009030025-R; Package: 0402; Part_type: CAPACITORS\CERAMIC; Project: G4_SVGA; RoHS: RoHS; Temperature: -55°C+125°C; Tolerance: 10%; Voltage: 50V; Wattage: NA; Weight: 0.65mg; Datasheet: Y:\MIS_DATABASE\DATASHEETS\CAPACITORS\GRM155R71H103KA88D.PDF
C237 = CAP: CAP CERAMIC 220pF 100V 5% C0G(NP0) 0402; Chkd/date: MANIRAJA/061021; Crtd /date: ALVY/051021; Custom_Duty: 15%; Customs_HS_Code: 85322990; Distributor_name: DIGIKEY; Distributor_part_number: 490-GRM1555C2A221JE01DTR-ND; Footprint Path: Y:\MIS_DATABASE\Library\ALTIUM_TOOL\PCB_FOOTPRINTS\Altium_Footprint_Lib.PcbLib; Height: 0.55MM; Library Path: Y:\MIS_DATABASE\Library\ALTIUM_TOOL\SCHEMATICS_PARTS\MS_DISCRETE_Library.schlib; Mfr_name: MURATA; Mfr_part_number: GRM1555C2A221JE01D; Mistral Part No: 120021100001-R; Package: 0402; Part_type: CAPACITORS\CERAMIC; Project: TI_AM62x SKEVM_BRD; RoHS: RoHS; Temperature: -55°C+125°C; Tolerance: 5%; Voltage: 100V; Wattage: NA; Weight: 1.6mg; Datasheet: Y:\MIS_DATABASE\DATASHEETS\CAPACITORS\GRM1555C2A221JE01.PDF
D6 D7 = DIODE: DIODE SWITCH 400mW 100V SOD123; Chkd/date: VASANTHA/220317; Crtd /date: MANIRAJA/150317; Custom_Duty: 15%; Customs_HS_Code: 85412900; Distributor_name: DIGIKEY; Distributor_part_number: 1N4148W-FDICT-ND; Height: 1.35MM; Mfr_name: DIODES INC; Mistral Part No: 130009030246-R; Package: SOD123; Part_type: DIODE\SWITCHING; Project: REVA-IBMS; RoHS: RoHS; Temperature: -65°C+150°C; Tolerance: NA; Voltage: 100V; Wattage: 400mW; Weight: 0.01g; Datasheet: Y:\MIS_DATABASE\DATASHEETS\DISCRETES\DIODES\1N4148W.PDF
FL6 = EMIFILTER_IND: PASSIVE FILTER EMI 100E 2A 0603; Chkd/date: BAVISH/170811; Crtd /date: CHAITHANYA/170811; Custom_Duty: 24%; Customs_HS_Code: 85437099; Distributor_name: DIGIKEY; Distributor_part_number: BLM18EG101TN1D-ND; Footprint Path: Y:\MIS_DATABASE\Library\ALTIUM_TOOL\PCB_FOOTPRINTS\Altium_Footprint_Lib.PcbLib; Height: 0.65MM; Library Path: Y:\MIS_DATABASE\Library\ALTIUM_TOOL\SCHEMATICS_PARTS\MS_FILTER_Library.schlib; Mfr_name: MURATA; Mfr_part_number: BLM18EG101TN1D; Mistral Part No: 130011080028-R; Package: 0603; Part_type: FILTER; Project: CPCI3GADC_CARD; RoHS: RoHS; Temperature: -55°C+125°C; Tolerance: NA; Voltage: NA; Wattage: NA; Weight: NA; Datasheet: Y:\MIS_DATABASE\DATASHEETS\DISCRETES\INDUCTORS\BLM18E.PDF
J9 = HEADER_2X1: CON HDR 2X1 2.54MM PITCH ST TH; Chkd/date: NAVEED/210714; Crtd /date: USMAN/031012; Custom_Duty: 24%; Customs_HS_Code: 85369090; Distributor_name: DIGIKEY; Distributor_part_number: WM8072-ND; Height: 5.60MM; Mfr_name: MOLEX; Mfr_part_number: 90120-0122; Mistral Part No: 150012100005-R; Package: THRU-HOLE; Part_type: CONNECTOR\HEADERS; Project: NPOL_FEP; RoHS: RoHS; Temperature: -55°C+125°C; Tolerance: NA; Voltage: NA; Wattage: NA; Weight: NA; Datasheet: Y:\MIS_DATABASE\DATASHEETS\CONNECTORS\90120-SERIES.PDF
J10 = HEADER_3X1: CON HDR 1X3 2.54MM PITCH ST TH; Chkd/date: VASANTHA/211015; Crtd /date: VASANTHA/211015; Custom_Duty: 24%; Customs_HS_Code: 85369090; Distributor_name: DIGIKEY; Distributor_part_number: 732-5316-ND; Height: 8.54MM; Mfr_name: WURTH ELECTRONICS INC; Mfr_part_number: 61300311121; Mistral Part No: 150015100037-R; Package: THRU-HOLE; Part_type: CONNECTOR\HEADERS; Project: CYPHY_ROADKILL; RoHS: RoHS; Temperature: NA; Tolerance: NA; Voltage: NA; Wattage: NA; Weight: NA; Datasheet: Y:\MIS_DATABASE\DATASHEETS\CONNECTORS\6130XXX.PDF
R271-R275 R283 R284 = RESISTOR: RES 0E 1/10W JUMPER 0402; Assembly_Instruction: DNI; Chkd/date: VASANTHA/061216; Crtd /date: NAVEED/201014; Custom_Duty: 15%; Customs_HS_Code: 85332119; Distributor_name: DIGIKEY; Distributor_part_number: P0.0JCT-ND; Footprint Path: Y:\MIS_DATABASE\Library\ALTIUM_TOOL\PCB_FOOTPRINTS\Altium_Footprint_Lib.PcbLib; Height: 0.40MM; IBISSP_MODLES: VALUE REPEATING 2 TIME; Library Path: Y:\MIS_DATABASE\Library\ALTIUM_TOOL\SCHEMATICS_PARTS\MS_DISCRETE_Library.schlib; Mfr_name: PANASONIC-ECG; Mfr_part_number: ERJ-2GE0R00X; Mistral Part No: 110018030052-R; Package: 0402; Part_type: RESISTORS\FIXED; Project: AEGIS POM; RoHS: RoHS; Temperature: -55°C+155°C; Tolerance: NA; Voltage: NA; Wattage: 1/10W; Weight: 0.8mg; Datasheet: Y:\MIS_DATABASE\DATASHEETS\RESISTORS\PAN-ERJSER_NOV17.PDF
R279 R280 = RESISTOR: RES 10K 1/16W 5% 0402; Assembly_Instruction: DNI; Chkd/date: VASANTHA/061216; Crtd /date: MAZHAR/230805; Custom_Duty: 15%; Customs_HS_Code: 85332119; Distributor_name: DIGIKEY; Distributor_part_number: 311-10KJRCT-ND; Footprint Path: Y:\MIS_DATABASE\Library\ALTIUM_TOOL\PCB_FOOTPRINTS\Altium_Footprint_Lib.PcbLib; Height: 0.40MM; Library Path: Y:\MIS_DATABASE\Library\ALTIUM_TOOL\SCHEMATICS_PARTS\MS_DISCRETE_Library.schlib; Mfr_name: YAGEO AMERICA; Mfr_part_number: RC0402JR-0710KL; Mistral Part No: 110011060021-R; Package: 0402; Part_type: RESISTORS\FIXED; Project: HSE; RoHS: RoHS; Temperature: -55°C+155°C; Tolerance: 5%; Voltage: NA; Wattage: 1/16W; Weight: 0.65mg; Datasheet: Y:\MIS_DATABASE\DATASHEETS\RESISTORS\RCXXXXL-SER_MAR18.PDF
SW4 = SWTACT_CAS-120TA: SWITCH TACT SPST SMD; Chkd/date: MAZHAR/221108; Crtd /date: USMAN/171008; Custom_Duty: 24%; Customs_HS_Code: 85369090; Distributor_name: DIGIKEY; Distributor_part_number: CAS120JCT-ND; Height: 2.50MM; Mfr_name: COPAL ELECTRONICS; Mistral Part No: 130009030342; Package: SMD; Part_type: ELECTRO-MECHANICAL\SWITCH; Project: SMART VIEW_IP CAMERA; Datasheet: Y:\MIS_DATABASE\DATASHEETS\MISC\SWITCHES\CAS-XX.PDF
SW5 = SW2_CHS-01TA: SWITCH SLIDE 1POS SPST SMD; Chkd/date: MANIRAJA/031018; Crtd /date: MANIRAJA/031018; Custom_Duty: 24%; Customs_HS_Code: 85369090; Distributor_name: DIGIKEY; Distributor_part_number: CKN10538CT-ND; Footprint Path: Y:\MIS_DATABASE\Library\ALTIUM_TOOL\PCB_FOOTPRINTS\Altium_Footprint_Lib.PcbLib; Height: 2.30MM; Library Path: Y:\MIS_DATABASE\Library\ALTIUM_TOOL\SCHEMATICS_PARTS\MS_SWITCH_Library.schlib; Mfr_name: CK; Mistral Part No: 130018100003-R; Package: SMD; Part_type: ELECTRO-MECHANICAL\SWITCH; Project: TI_60GHz-AOP; RoHS: RoHS; Temperature: -40°C+85°C; Tolerance: NA; Voltage: NA; Wattage: NA; Weight: NA; Datasheet: Y:\MIS_DATABASE\DATASHEETS\MISC\SWITCHES\TDAXX-SER.PDF
U41 = LMK1C1103_TSSOP8: IC 3-CHANNEL LVCMOS CLOCK BUFFER TSSOP8; Chkd/date: MANIRAJA/080920; Crtd /date: ALVY/070920; Custom_Duty: 15%; Customs_HS_Code: 85423100; Distributor_name: DIGIKEY; Distributor_part_number: 296-LMK1C1103PWRCT-ND; Footprint Path: Y:\MIS_DATABASE\Library\ALTIUM_TOOL\PCB_FOOTPRINTS\Altium_Footprint_Lib.PcbLib; Height: 1.20MM; Library Path: Y:\MIS_DATABASE\Library\ALTIUM_TOOL\SCHEMATICS_PARTS\MS_COMBINATIONAL_Library.schlib; Mfr_name: TEXAS INSTRUMENTS; Mistral Part No: 141020090002-R; Package: TSSOP8; Part_type: ICS\DIGITAL\COMBINATIONAL; Project: AM64X_SKEVM; RoHS: RoHS; Temperature: -40°C+125°C; Tolerance: NA; Voltage: NA; Wattage: NA; Weight: 34.1mg; Datasheet: Y:\MIS_DATABASE\DATASHEETS\ICS\DIGITAL\COMBINATIONAL\LMK1C110X.PDF
U42 = OSC4_EQXP-HC33: OSC 25.000MHz 3.3V CMOS SMD; Chkd/date: MANIRAJA/070121; Crtd /date: ALVY/060121; Custom_Duty: 24%; Customs_HS_Code: 85437099; Distributor_name: NA; Distributor_part_number: NA; Footprint Path: Y:\MIS_DATABASE\Library\ALTIUM_TOOL\PCB_FOOTPRINTS\Altium_Footprint_Lib.PcbLib; Height: 1.20MM; Library Path: Y:\MIS_DATABASE\Library\ALTIUM_TOOL\SCHEMATICS_PARTS\MS_DISCRETE_Library.schlib; Mfr_name: WURTH ELEKTRONIK; Mfr_part_number: 831055678; Mistral Part No: 130021010008-R; Package: SMD; Part_type: OSCILLATORS; Project: TI_AM243x LP EVM; RoHS: RoHS; Temperature: -40°C+85°C; Tolerance: NA; Voltage: 3.3V; Wattage: NA; Weight: NA; Datasheet: Y:\MIS_DATABASE\DATASHEETS\MISC\CRY_OSC\831055678.PDF
U43 = SN74LVC1G07DBVR_SOT23-5: IC SINGLE BUFFER GATE CMOS LOGIC LEVEL SHIFTER SC70-5; Chkd/date: MANIRAJA/130819; Crtd /date: MANIRAJA/130819; Custom_Duty: 15%; Customs_HS_Code: 85423100; Distributor_name: DIGIKEY; Distributor_part_number: 296-37177-1-ND; Footprint Path: Y:\MIS_DATABASE\Library\ALTIUM_TOOL\PCB_FOOTPRINTS\Altium_Footprint_Lib.PcbLib; Height: 1.10MM; Library Path: Y:\MIS_DATABASE\Library\ALTIUM_TOOL\SCHEMATICS_PARTS\MS_GATE_Library.schlib; Mfr_name: TEXAS INSTRUMENTS; Mistral Part No: 141019080005-R; Package: SC70-5; Part_type: ICS\DIGITAL\GATES; Project: BRUKER_SD820_COMMONDO; RoHS: RoHS; Temperature: -40°C+125°C; Tolerance: NA; Voltage: NA; Wattage: NA; Weight: 20mg; Datasheet: Y:\MIS_DATABASE\DATASHEETS\ICS\DIGITAL\GATES\SN74LV1T34.PDF
U44 = SN74CB3Q3257PWR_TSSOP16: IC 4BIT 1-OF-2 FET MULTIPLEXER/DEMULTIPLEXER TSSOP16; Chkd/date: SUHAS/251010; Crtd /date: USMAN/060109; Custom_Duty: 15%; Customs_HS_Code: 85423100; Distributor_name: DIGIKEY; Distributor_part_number: 296-19138-1-ND; Height: 1.20MM; Mfr_name: TEXAS INSTRUMENTS; Mistral Part No: 141009030117-R; Package: TSSOP16; Part_type: ICS\DIGITAL\COMBINATIONAL; Project: OMAP_EVM; RoHS: Sb/ Br FREE; Temperature: -40°C+85°C; Datasheet: Y:\MIS_DATABASE\DATASHEETS\ICS\DIGITAL\COMBINATIONAL\SN74CB3Q3257.PDF
U45 = TLIN2029DQ1_SOIC8: IC FAULT PROTECTED LIN TRANSCEIVER WITH DOMINANT STATE TIMEOUT SOIC8; Chkd/date: MANIRAJA/140818; Crtd /date: ALVY/140818; Custom_Duty: 15%; Customs_HS_Code: 85423100; Distributor_name: DIGIKEY; Distributor_part_number: 296-49967-ND; Footprint Path: Y:\MIS_DATABASE\Library\ALTIUM_TOOL\PCB_FOOTPRINTS\Altium_Footprint_Lib.PcbLib; Height: 1.75MM; Library Path: Y:\MIS_DATABASE\Library\ALTIUM_TOOL\SCHEMATICS_PARTS\MS_TELECOM_Library.schlib; Mfr_name: TEXAS INSTRUMENTS; Mfr_part_number: TLIN2029DQ1; Mistral Part No: 143018080003-R; Package: SOIC8; Part_type: ICS\TELECOM\TRANSCEIVER; Project: TI_J7ES_GESI_BOARD; RoHS: RoHS; Temperature: -40°C+125°C; Tolerance: NA; Voltage: NA; Wattage: NA; Weight: NA; Datasheet: Y:\MIS_DATABASE\DATASHEETS\ICS\TELECOM\TLIN2029-Q1.PDF

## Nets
DGND: C101.2 C102.2 C103.2 C104.2 C105.2 C106.2 C107.2 C108.2 C109.2 C110.2 C111.2 C112.2 C113.2 C114.2 C115.2 C116.2 C117.2 C118.2 C119.2 C120.2 C121.2 C122.2 C123.2 C124.2 C125.2 C126.2 C127.2 C128.2 C129.2 C130.2 C131.2 C132.2 C133.2 C134.2 C135.2 C136.2 C137.2 C138.2 C139.2 C140.2 C141.2 C142.2 C143.2 C144.2 C145.2 C146.2 C147.2 C148.2 C149.2 C150.2 C151.2 C152.2 C153.2 C154.2 C155.2 C156.2 C220.2 C221.2 C222.2 C225.2 C226.2 C230.2 C231.2 C232.2 C233.2 C234.2 C235.2 C236.2 C237.2 C3746.2 J8.1 J8.5 J8.8 J8.15 J8.16 J8.17 J8.18 J8.21 J8.24 J8.31 J8.32 J8.33 J8.34 J8.41 J8.SH1 J8.SH2 J8.SH3 J8.SH4 J9.2 J10.3 R63.2 R82.2 R264.1 R266.1 R279.2 R280.2 R281.2 R3870.1 R3871.1 R3874.2 R3875.2 U1.A1(VSS) U1.A18(VSS) U1.E5(VSS) U1.E6(VSS) U1.E7(VSS) U1.E8(VSS) U1.E10(VSS) U1.E12(VSS) U1.E13(VSS) U1.E14(VSS) U1.F5(VSS) U1.F6(VSS) U1.F7(VSS) U1.F8(VSS) U1.F10(VSS) U1.F12(VSS) U1.F13(VSS) U1.F14(VSS) U1.G7(VSS) U1.G8(VSS) U1.G9(VSS) U1.G10(VSS) U1.G11(VSS) U1.G12(VSS) U1.H5(VSS) U1.H6(VSS) U1.H7(VSS) U1.H8(VSS) U1.H9(VSS) U1.H10(VSS) U1.H11(VSS) U1.H12(VSS) U1.H13(VSS) U1.H14(VSS) U1.J5(VSS) U1.J6(VSS) U1.J7(VSS) U1.J8(VSS) U1.J9(VSS) U1.J10(VSS) U1.J11(VSS) U1.J12(VSS) U1.J13(VSS) U1.J14(VSS) U1.K7(VSS) U1.K8(VSS) U1.K9(VSS) U1.K10(VSS) U1.K11(VSS) U1.K12(VSS) U1.L5(VSS) U1.L6(VSS) U1.L7(VSS) U1.L8(VSS) U1.L9(VSS) U1.L10(VSS) U1.L11(VSS) U1.L12(VSS) U1.L13(VSS) U1.L14(VSS) U1.M5(VSS) U1.M6(VSS) U1.M7(VSS) U1.M8(VSS) U1.M9(VSS) U1.M10(VSS) U1.M11(VSS) U1.M12(VSS) U1.M13(VSS) U1.M14(VSS) U1.N7(VSS) U1.N8(VSS) U1.N9(VSS) U1.N10(VSS) U1.N11(VSS) U1.N12(VSS) U1.P5(VSS) U1.P6(VSSA) U1.P8(VSSA) U1.P10(VSSA) U1.P12(VSSA) U1.P13(VSS) U1.P14(VSS) U1.R5(VSSA) U1.R13(VSSA) U1.T2(VSS) U1.V1(VSSA) U1.V18(VSSA) U39.3(GND) U41.4(GND) U42.2(GND) U43.3(GND) U44.8(GND) U45.5(GND) U90.5(GND) ; also on sheet 1 2 3 4 6 10 11 12 13 14 15 16 17 24 25 26 27 28 29 30 32 33
VBAT_LIN: D7.2(A) J9.1
VCC_1V2: C102.1 C103.1 C110.1 C111.1 C112.1 C113.1 C114.1 C115.1 C116.1 C117.1 C118.1 C119.1 C120.1 C121.1 C122.1 C123.1 C124.1 C125.1 C126.1 C127.1 C128.1 C129.1 C130.1 C131.1 C132.1 C133.1 U1.D10(VDDAR2) U1.E9(VDD) U1.E11(VDD) U1.F9(VDD) U1.F11(VDD) U1.G5(VDD) U1.G6(VDD) U1.G13(VDD) U1.G14(VDD) U1.H3(VDDAR3) U1.J15(VDDAR1) U1.J16(VDD) U1.K5(VDD) U1.K6(VDD) U1.K13(VDD) U1.K14(VDD) U1.N5(VDD) U1.N6(VDD) U1.N13(VDD) U1.N14(VDD) U1.R9(VDD_F) ; also on sheet 1
VDD_2V5: C220.1 C221.1 J8.4 J8.6 ; also on sheet 14 15
VDD_5V0_LDO3: SW4.1 ; also on sheet 12 13 30
VDD_IO_3V3: C138.1 C139.1 C147.1 C148.1 C149.1 C150.1 C151.1 C152.1 C153.1 C154.1 C155.1 C156.1 FL1.1 U1.D8(VDDS33) U1.D12(VDDS33) U1.H4(VDDS33) U1.H15(VDDS33) U1.L15(VDDS33) U1.P4(VDDS33) U1.R15(VDDS33) ; also on sheet 1
VDDA1V8_OSC_PLL_F: C146.1 FL2.2 U1.R4(VDDA18_OSC_PLL)
VDDA3V3_F: C134.1 C135.1 C136.1 C137.1 FL1.2 U1.P7(VDDA33) U1.P9(VDDA33) U1.P11(VDDA33)
VDDA_IO_1V8: C140.1 C141.1 C142.1 C143.1 C144.1 C145.1 FL2.1 R467.1 U1.R6(VDDA18_LDO) U1.R8(VDDA18) U1.R11(VDDA18) ; also on sheet 16
VDDIO: C225.1 C226.1 J8.44 J8.46 ; also on sheet 14 15
VDDS_IO_1V8: C104.1 C105.1 C106.1 C107.1 C108.1 C109.1 U1.D6(VDDS18) U1.E15(VDDS18) U1.L4(VDDS18) U1.N15(VDDS18) U1.T3(VDDS18_LDO) U43.5(VCC)
1588_SFD: J8.38 ; also on sheet 27
CLK_BUF_EN: R276.1 U41.2(1G) ; also on sheet 12
CLOCKOUT0: R271.1 ; also on sheet 27
ETH_EEPROM_A0: J8.47 R3875.1
ETH_EEPROM_A2: J8.37 R3874.1
EXT_VMON2: J8.2 ; also on sheet 30
GPIO_2/CLKOUT: J8.48
GPIO_ICSSM2_RST: R265.1 U39.1(A) ; also on sheet 12
HSEC_UART1_RXD: U44.3(1B2) ; also on sheet 6
HSEC_UART1_TXD: U44.6(2B2) ; also on sheet 6
I2C0_SCL: J8.40 ; also on sheet 26
I2C0_SDA: J8.42 ; also on sheet 26
ICSSM2_PWDN/INTn: J8.10 R267.1 ; also on sheet 27
ICSSM2_RESETn: J8.12 R266.2 U39.4(Y)
ICSSM_BRD_CONN_DET: J8.36 R263.1
ICSSM_INH: J8.26 R264.2
ICSSM_MII0/MII1_COL_ADD: J8.14 ; also on sheet 33
ICSSM_MII0/MII1_CRS_ADD: J8.30 ; also on sheet 33
ICSSM_MII0/MII1_RXCLK_ADD: J8.19 ; also on sheet 33
ICSSM_MII0/MII1_RXD0_ADD: J8.23 ; also on sheet 33
ICSSM_MII0/MII1_RXD1_ADD: J8.25 ; also on sheet 33
ICSSM_MII0/MII1_RXD2_ADD: J8.27 ; also on sheet 33
ICSSM_MII0/MII1_RXD3_ADD: J8.29 ; also on sheet 33
ICSSM_MII0/MII1_RXDV_ADD: J8.45 ; also on sheet 33
ICSSM_MII0/MII1_RXER_ADD: J8.39 ; also on sheet 33
ICSSM_MII0/MII1_RXLINK_ADD: J8.43 ; also on sheet 33
ICSSM_MII0/MII1_TXCLK_ADD: J8.3 ; also on sheet 33
ICSSM_MII0/MII1_TXD0_ADD: J8.7 ; also on sheet 33
ICSSM_MII0/MII1_TXD1_ADD: J8.9 ; also on sheet 33
ICSSM_MII0/MII1_TXD2_ADD: J8.11 ; also on sheet 33
ICSSM_MII0/MII1_TXD3_ADD: J8.13 ; also on sheet 33
ICSSM_MII0/MII1_TXEN_ADD: J8.35 ; also on sheet 33
LIN_EN: R285.1 U45.2(EN)
LIN_MUX_OE#: R280.1 U44.15(~{OE})
LIN_MUX_SEL: R277.2 R279.1 U44.1(S) ; also on sheet 12
LIN_UART1_RXD: R284.1 U44.2(1B1)
LIN_UART1_TXD: R283.1 U44.5(2B1)
MDIO0_MDC: U90.3(A1) ; also on sheet 12 15
MDIO0_MDIO: U90.7(B1) ; also on sheet 12 15
MDIO/MDC_MUX_SEL2: R3871.2 U90.1(SEL) ; also on sheet 12
MUX_UART1/LIN_RXD: U44.4(1A) ; also on sheet 26
MUX_UART1/LIN_TXD: U44.7(2A) ; also on sheet 26
OSC_CLK_OUT: R273.1 U42.3(OUTPUT)
PORZ: U39.2(B) ; also on sheet 6 10 11 15 24 27
PR0_MDIO0_MDC: U90.2(A0) ; also on sheet 15
PR0_MDIO0_MDC_ADD: J8.20 R3867.2 U90.4(A)
PR0_MDIO0_MDIO: U90.8(B0) ; also on sheet 15
PR0_MDIO0_MDIO_ADD: J8.22 R3866.2 U90.6(B)
PR0_PRU0_REF_CLK: R272.2 ; also on sheet 15
PR0_PRU1_GPIO0: R247.2 ; also on sheet 32
PR0_PRU1_GPIO1: R248.2 ; also on sheet 32
PR0_PRU1_GPIO2: R249.2 ; also on sheet 32
PR0_PRU1_GPIO3: R250.2 ; also on sheet 32
PR0_PRU1_GPIO4: R251.2 ; also on sheet 32
PR0_PRU1_GPIO5: R252.2 ; also on sheet 32
PR0_PRU1_GPIO6: R253.2 ; also on sheet 32
PR0_PRU1_GPIO8: R254.2 ; also on sheet 32
PR0_PRU1_GPIO9: R255.2 ; also on sheet 32
PR0_PRU1_GPIO10: R256.2 ; also on sheet 32
PR0_PRU1_GPIO11: R257.2 ; also on sheet 32
PR0_PRU1_GPIO12: R258.2 ; also on sheet 32
PR0_PRU1_GPIO13: R259.2 ; also on sheet 32
PR0_PRU1_GPIO14: R260.2 ; also on sheet 32
PR0_PRU1_GPIO15: R261.2 ; also on sheet 32
PR0_PRU1_GPIO16: R262.2 ; also on sheet 32
PR0_PRU1_GPIO18: R1652.2 ; also on sheet 6
PR0_PRU1_GPIO19: R1653.2 ; also on sheet 6
PR0_PRU1_REF_CLK: J8.28 R274.2
RSVD_T4: R82.1 U1.T4(RSVD)
SOC_CLK_IN: U43.4(Y) ; also on sheet 27
VLIN: C236.1 D6.2(A) J10.1 SW4.2(COM) U45.7(VSUP)
VPP_1V7: R63.1 R83.1 ; also on sheet 29
VPP_R: C101.1 R83.2 R467.2 TP86.1(TP) U1.N3(VPP)
VSYS_3V3_LDO1: C222.1 C230.1 C233.1 C3746.1 FL6.1 R263.2 R265.2 R267.2 R276.2 R3866.1 R3867.1 U39.5(VCC) U42.1(ENABLE/DISABLE) U42.4(VDD) U90.10(VCC) ; also on sheet 1 6 10 11 12 13 14 15 16 17 24 26 27 28 29 30 32 33
VSYS_3V3_LDO2: C234.1 R277.1 R282.1 R285.2 U44.16(VCC) ; also on sheet 1 12 13 25 26 30
N32845049: C231.1 C232.1 FL6.2 U41.6(VDD)
N32845083: R271.2 R273.2 U41.1(CLKIN)
N32845192: R272.1 U41.3(Y0)
N32845194: R274.1 U41.8(Y1)
N32845196: R275.1 U41.5(Y2)
N33770351: R275.2 U43.2(A)
N33879812: R283.2 U45.4(TXD)
N33879815: R282.2 R284.2 U45.1(RXD)
N33880944: R281.1 U44.9(3A) U44.12(4A)
N33881371: C237.1 J10.2 SW5.1 U45.6(LIN)
N33882160: D6.1(K) R278.1
N33883080: R278.2 SW5.2
N33986982: C235.1 D7.1(K) SW4.3
N35805242: R247.1 U1.F18(PR0_PRU1_GPIO0)
N35805430: R255.1 U1.C18(PR0_PRU1_GPIO9)
N35805533: R248.1 U1.G16(PR0_PRU1_GPIO1)
N35805539: R249.1 U1.E17(PR0_PRU1_GPIO2)
N35805550: R250.1 U1.E18(PR0_PRU1_GPIO3)
N35805561: R251.1 U1.F16(PR0_PRU1_GPIO4)
N35805574: R252.1 U1.F15(PR0_PRU1_GPIO5)
N35805586: R253.1 U1.E16(PR0_PRU1_GPIO6)
N35805597: R254.1 U1.D18(PR0_PRU1_GPIO8)
N35805610: R256.1 U1.D17(PR0_PRU1_GPIO10)
N35805636: R257.1 U1.B18(PR0_PRU1_GPIO11)
N35805639: R258.1 U1.B17(PR0_PRU1_GPIO12)
N35805644: R259.1 U1.D16(PR0_PRU1_GPIO13)
N35805649: R260.1 U1.C17(PR0_PRU1_GPIO14)
N35805656: R261.1 U1.A17(PR0_PRU1_GPIO15)
N35805662: R262.1 U1.C16(PR0_PRU1_GPIO16)
N35805667: R1652.1 U1.C15(PR0_PRU1_GPIO18)
N35805672: R1653.1 U1.D15(PR0_PRU1_GPIO19)
N35842882: R3870.2 U90.9(~{EN})

Not connected (* = marked no-connect by the designer): U41 7(NC)*; U43 1(NC)*; U44 10(3B2)* 11(3B1)* 13(4B2)* 14(4B1)*; U45 3(NC1)* 8(NC2)*

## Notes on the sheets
sheet 7
- PRU1 ICSS MII1 Ethernet
- CAD NOTE: Place the resistors close to SoC with minimum stub
- Note: Net/Signal on pin 48 is not supported on AM263P
- DF40GB-48DP-0.4V(58)
- Ethernet connector I2C Address - 0x52
- CAD NOTE: Add Silkscreen 'Ethernet Connector 0' next to J8 Connector
- RESET
- From IO Exp
- MDIO/MDC MUX FOR ADD-ON BOARD CONN
sheet 8
- SOC-POWER and GND
- CAD NOTE: PLACE A 0.1uF CAP  CLOSE
  AS POSSIBLE TO VPP PIN (N3).
- NOTE:
- VPP = 1.7V  FROM ANALDO OF SOC (Re-Programmed to 1.7V)
- MOUNT R467 & DEMOUNT R83
- MOUNT R83 & DEMOUNT R467
- VPP = 1.7V  FROM EXT LDO (U66)
sheet 9
- CLOCKS
- LIN MUX/DEMUX
- LIN 1
- I2C0 - 1:2  MUX
- SILK: VBAT
- SEL
- CONDITION
- FUNCTION
- SILK: LIN
- LOW
- LIN SELECTED
- A-->B1 port
- HIGH
- HSEC UART selected
- A-->B2 port
- LIN MASTER MODE
- Switch - CLOSE
- LIN SLAVE MODE
- Switch - OPEN
